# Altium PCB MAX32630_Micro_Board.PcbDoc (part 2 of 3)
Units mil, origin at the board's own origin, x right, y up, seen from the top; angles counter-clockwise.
Board outline 1192.91 x 1079.23 mil, 6 copper layers (Top Layer, Ground Plane +, Mid-Layer 2, Mid-Layer 3, Power Plane 1.8v, Bottom Layer), stack 51.6 mil thick; 105 components, 122 nets, 1109 pads, 512 vias.
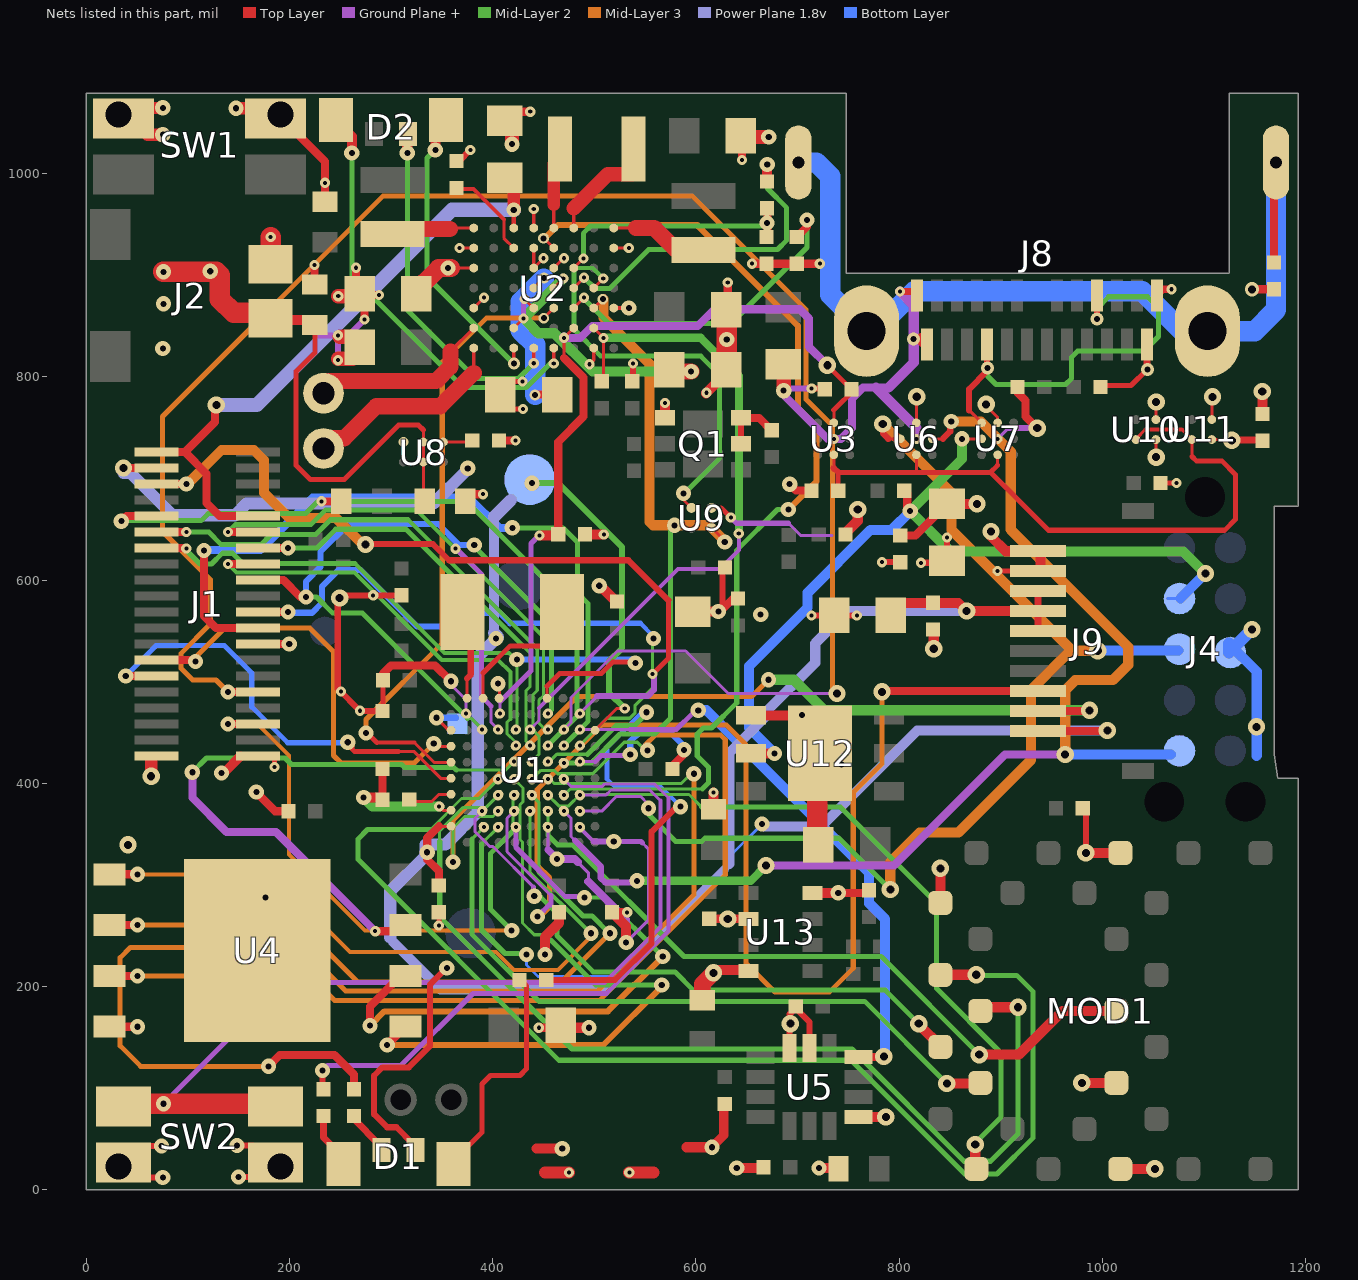
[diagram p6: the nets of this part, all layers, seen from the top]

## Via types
v1: diameter 15, hole 6, Top Layer to Bottom Layer, tented both sides, 180 vias
v2: diameter 10, hole 4, Top Layer to Ground Plane +, tented both sides, 134 vias
v3: diameter 17, hole 8, Top Layer to Bottom Layer, tented both sides, 82 vias
v4: diameter 10, hole 4, Ground Plane + to Mid-Layer 2, tented both sides, 57 vias
v5: diameter 12.8, hole 6, Top Layer to Bottom Layer, tented both sides, 20 vias
v6: diameter 10, hole 4, Top Layer to Ground Plane +, tented top, 16 vias
v7: diameter 10.63, hole 5.91, Top Layer to Bottom Layer, tented both sides, 13 vias
v8: diameter 10, hole 4, Ground Plane + to Mid-Layer 2, 5 vias
v9: diameter 11.81, hole 5.91, Top Layer to Bottom Layer, tented both sides, 3 vias
v10: diameter 14.17, hole 6, Top Layer to Bottom Layer, tented both sides, 1 vias
v11: diameter 14, hole 8, Top Layer to Bottom Layer, tented both sides, 1 vias

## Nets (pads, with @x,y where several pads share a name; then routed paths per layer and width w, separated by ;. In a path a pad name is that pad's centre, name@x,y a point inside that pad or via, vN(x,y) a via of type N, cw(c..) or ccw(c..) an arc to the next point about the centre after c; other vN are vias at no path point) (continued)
3V: C9.1 C12.2 C19.1 C37.1 D1.2 J1.4 J9.6 J9.7 J9.8 U1.A2 U2.A5 | length 2295.2
  Top Layer w3: 347.17,357.67 U1.A2@359.02,357.67 ; v1@358.74,907.13 U2.A5@381.39,907.13
  Top Layer w6: D1.2@321.33,45.39 305.33,61.39 296.18,61.39 283.39,74.18 283.39,112.39 291.39,120.39 317.38,120.39 338.5,141.51 338.5,202 353.92,217.42 354.86,216.48 v1(354.86,218.06)
  Top Layer w7: J9.6@936.69,549.84 J9.7@936.69,569.53 J9.8@936.69,589.21
  Top Layer w8: v3(36.64,710.25) J1.4@69,710.25 ; C19.1@347,299.5 347,313.78 335.55,325.23 335.55,346.05 347.17,357.67
  Top Layer w10: C37.1@790.5,568.52 799.48,577.5 858.5,577.5 v3(866.5,569.5) J9.7@928.5,569.5
  Top Layer w18: C9.1@321.33,881.39 347.07,907.13 v1@358.74,907.13
  Power Plane 1.8v w8: 513.4,201.18 633.02,320.8
  Power Plane 1.8v w10: 302.12,243.75 348.78,197.1 509.31,197.1 513.4,201.18 ; v1@401.39,547.78 401.39,662.03 ; 633.02,320.8 633.02,429.76 667.96,464.7 667.96,469.13 717.51,518.68 717.51,537.66 749.38,569.53 ; 749.4,569.5 v3(866.5,569.5)
  Power Plane 1.8v w12: v3@36.64,705.67 43.25,705.67 85.04,663.89 146.19,663.89 157.69,675.39 341.89,675.39 v1@375.5,709 ; 299.27,248.27 299.27,293.93 334.07,328.73 334.07,339.69 v1@335.23,338.53 ; v1@335.23,338.51 335.38,338.37 v1@335.68,338.07 ; v1@335.23,339.39 v1@335.23,338.53 ; v1@401.39,547.78 405.2,543.97 v1@403.62,542.39 ; 401.39,662.03 418.07,678.71 ; v1(403.39,542.39) v1@403.62,542.39 ; v1@335.23,338.53 v1@335.38,338.39 ; v1@335.23,338.53 v1@335.38,338.39 ; v1@335.38,338.39 336.68,339.69 353.69,339.69 385.39,371.39 385.39,524.16 v1@403.62,542.39
  other v1: 335.55,332.08 375.5,710 355.93,907.12
3V3_SFO: C10.2 C11.2 C17.1 C27.1 C47.1 R18.1 U1.D9 U2.F2 U3.C2 U6.C2 U7.C2 U10.B1 U11.B1 | length 1054.6
  Top Layer w3: C17.1@463.5,644 C17.1@464.5,645 ; 470.18,818.7 v6(470.18,838.44) U2.F2@479.81,848.07 ; v3@729.39,811.39 v3(729.39,811.48) ; U3.C2@735.75,754.75 735.75,767.36 ; C11.2@752.39,788.39 C11.2@756.78,788.39 ; U6.C2@817,754.75 v3@817,783 ; v3@877.5,675 v3@878,675.5 ; v3@886,771 897,760 U7.C2@897,754.75 ; v3@1053,724 U10.B1@1053,738.31 ; U11.B1@1108,738.31 1127.31,738.31 v3@1127.63,738
  Top Layer w5: v3@729.39,811.39 C11.2@752.39,788.39 ; 735.75,767.36 C11.2@756.78,788.39
  Top Layer w7: v3@1127.63,738 C10.2@1157.78,738
  Top Layer w8: C17.1@464.5,645 464.5,736 489.39,760.89 489.39,799.5 470.18,818.7 ; v1(692.31,694.39) 698.7,688 R18.1@715,688 ; C27.1@801.25,644 816.15,644 C47.1@847.15,675
  Top Layer w10: v2(446,644) C17.1@463.5,644 ; C47.1@847.15,675 v3(876.68,675) v3@877.5,675
  Ground Plane + w3: v8(407.16,468.79) 407.16,480.16
  Ground Plane + w5: 407.16,480.16 437.68,510.68 437.68,636.04 v2@446.64,645
  Ground Plane + w8: v6(470.18,838.44) 486.18,838.39 497.96,850.17 601.89,850.17 618.22,866.5 702.32,866.5 711.46,857.36 711.46,829.41 v3(729.39,811.48)
  Ground Plane + w10: v6(470.18,838.44) v6(470.18,838.44)
  other v3: 1053,721 1127.5,737.5 885.68,772.99 817.39,780.39
  other v6: 407.16,468.79
5V0_B: C38.1 J1.2 J1.9 U2.C7 | length 639.1
  Top Layer w3: C38.1@409.39,994.39 C38.1@420.76,983.02
  Top Layer w4: U2.C7@420.76,946.5 v10(420.76,964.39)
  Top Layer w8: J1.2@69,726 97,726 ; v3@126.61,773.61 126.61,755.61 97,726 ; J1.9@169,663.01 131.27,663.01 118.39,675.89 118.39,704.61 97,726
  Top Layer w12: v10(420.76,964.39) C38.1@420.76,994.39
  Power Plane 1.8v w14: v3(128,772.21) 167.88,772.21 360.06,964.39 v10(420.76,964.39)
32KIN: U1.B10 X1.2 | length 81.3
  Top Layer w3: U1.B10@374.76,483.65 374.76,503.24 ; X1.2@374.76,562 374.76,542.41 X1.2@378.39,538.79
  Top Layer w6: 374.76,503.24 378.39,506.87 X1.2@378.39,538.79
32KOUT: U1.C10 X1.1 | length 120
  Top Layer w3: U1.C10@390.51,483.65 390.51,508.51
  Top Layer w5: 390.51,508.51 390.58,508.51 417.34,535.28 X1.1@456.53,535.28
  Top Layer w7: X1.1@456.53,535.28 X1.1@469.25,548
AIN0: J1.30 U1.A5 | length 439.7
  Top Layer w3: 307.39,431.39 322.39,431.39 348.86,404.91 U1.A5@359.02,404.91
  Top Layer w5: v1@261.39,441.39 261.39,433.89 263.89,431.39 307.39,431.39
  Top Layer w8: v1(38.89,505.53) J1.30@69,505.53
  Bottom Layer w5: v1(38.89,505.53) 68.88,535.52 135.83,535.52 162.89,508.46 162.89,475.22 198.22,439.89 v1@259.89,439.89
  other v1: 257.39,440.39
AIN1: U1.A6 U2.E3 | length 625.7
  Top Layer w3: v1@274.39,449.39 v1(275.39,449.39) ; 322.98,440.02 342.34,420.66 U1.A6@359.02,420.66 ; v7@449.96,857.59 U2.E3@460.13,867.76
  Top Layer w4: 285.98,440.02 322.98,440.02
  Top Layer w5: v1@276,450 285.98,440.02
  Mid-Layer 3 w5: v1(275.39,449.39) 275.39,462.78 350.39,537.78 350.39,814.39 394.13,858.13 v7@450.5,858.13
  Bottom Layer w5: v1(275.39,449.39) v1@276,450
  other v7: 450.37,857.76
AIN2: J1.28 U1.A7 | length 432.9
  Top Layer w3: v1@340.5,441.5 345.59,436.41 U1.A7@359.02,436.41
  Top Layer w8: J1.28@67.11,521.28 v1@106.11,521.28
  Mid-Layer 3 w5: v1(107.5,519.89) 107.5,524 136.27,552.77 220.01,552.77 243.39,529.39 243.39,427.39 250.89,419.89 322.89,419.89 v1(342,439)
AIN3: pad.2 U1.A8 | length 39
  Top Layer w3: v1@344.5,464.5 356.84,452.16 U1.A8@359.02,452.16
  Bottom Layer w6: v1(344.63,464.5) pad.2@363.99,464.5
BAT: C3.1 C40.1 J2.2 U2.H3 U8.A2 U8.B2 | length 568.8
  Top Layer w3: 331.84,747.66 U8.B2@331.84,716.16 331.84,678.66 C40.1@333,677.5
  Top Layer w4: U2.H3@519.18,867.76 v1@531.76,867.76
  Top Layer w5: C3.1@225,851 225,823.5 206.5,805 206.5,713 220.5,699 253.89,699 307.39,752.5 327,752.5 331.84,747.66
  Top Layer w10: J2.2@176.76,863 183.76,856 220,856 C3.1@225,851
  Top Layer w20: v1(75.89,903.39) 128.11,903.39 131.5,900 131.5,876.43 144.93,863 J2.2@176.76,863
  other v1: 534,867.76 122,904
DEBUG_ENABLE: R18.2 U3.A2 U6.A2 U7.A2 U10.A1 U11.A1 | length 668.9
  Top Layer w3: 735.75,710.25 U3.A2@735.75,723.25 ; R18.2@740,689.39 R18.2@741.39,688 ; 817,706 U6.A2@817,723.25 ; 897,713 U7.A2@897,723.25 ; U10.A1@1033.31,738.31 1033.31,739.18 1042.53,748.39 ; 1078.24,748.39 1088.31,738.31 1088.31,721.69
  Top Layer w4: 1042.53,748.39 1078.24,748.39
  Top Layer w5: R18.2@740,689.39 740,706 817,706 890,706 ; 897,713 890,706 ; 1088.31,721.69 1092.99,717.01 1117.99,717.01 1131,704 1131,659.5 1120.5,649 947,649 890,706
  Top Layer w6: 735.75,710.25 740,706
GND: C1.2 C2.2 C3.2 C4.2 C5.2 C6.2 C7.1 C8.1 C9.2 C10.1 C11.1 C12.1 C13.2 C14.2 C15.2 C16.2 C17.2 C18.2 C19.2 C20.2 C21.2 C22.2 C23.2 C24.2 C25.2 C26.2 C27.2 C28.2 C29.2 C30.2 C31.2 C32.2 C33.2 C34.2 C35.2 C36.2 C37.2 C38.2 C39.1 C40.2 C41.2 C42.2 C43.2 C44.2 C45.2 C46.2 C47.2 C48.2 J1.25 J1.39 J1.40 J2.1 J4.3 J8.A1 J8.A12 J8.B1 J8.B12 J9.9 J9.10 MOD1.1 MOD1.12 MOD1.14 MOD1.20 Q1.1 R2.1 R7.1 R11.2 R13.2 R19.1 RT1.1 SW1.3 SW1.4 SW2.3 SW2.4 U1.A3 U1.B9 U1.D10 U1.G2 U1.J2 U1.J6 U2.A3 U2.A6 U2.C2 U2.D3 U2.D5 U2.D6 U2.D7 U2.E5 U2.G1 U2.H6 U3.B2 U4.4 U4.EP U5.1 U5.6 U5.7 U6.B2 U7.B2 U8.A1 U9.B1 U10.B2 U11.B2 U12.1 U12.EP U13.1 U13.5 U13.7 | length 4527.6
  Top Layer w3: J1.39@169,426.79 181.49,426.79 J1.39@185.39,422.89 ; v2(181.5,937.5) v2@183.5,939.5 ; SW1.3@186.19,1051.95 SW1.3@195.05,1051.95 ; v2@231,678 v2(231.5,677.5) ; 290.39,392.39 291.61,391.17 C15.2@291.61,386 ; C22.2@291.61,471 C22.2@292,471.39 ; C44.2@292,501.39 C44.2@292,508 ; v2(347.39,377) 350.97,373.42 U1.A3@359.02,373.42 ; C39.1@364.39,1012.39 C39.1@367,1012.39 ; v2(367.39,926.81) U2.A6@381.39,926.81 ; C40.2@373,677.5 C40.2@380,684.5 ; U2.A3@381.39,867.76 v2(391.55,877.93) ; U1.D10@406.52,483.91 406.52,498 v1@407.62,498 ; U2.C2@420.76,848.07 v2@430.93,858.24 ; v2(431.22,876.55) U2.D3@441.39,866.39 ; U2.D6@440.44,926.81 U2.D5@440.44,907.13 v2@450.61,917.3 ; U2.D7@440.44,946.5 v2(440.44,965.39) ; U2.E5@460.13,907.13 v2@470.3,917.3 ; v6(495.39,812.39) 499.5,816.5 U2.G1@499.5,828.39 ; U2.H6@519.18,926.81 v2(534,926.81) ; C24.2@576.89,414 C24.2@576.89,417.28 ; U9.B1@615.39,671.07 624.83,671.07 ; v1(615.94,41.78) v1@616.39,41.78 ; v1(622.14,569) v1@626.39,573.25 ; C42.2@626.39,608 C42.2@628.78,610.39 ; U13.7@651.07,266.61 U13.7@652.01,267.55 ; U12.EP@703.98,417.4 U12.EP@714,407.39 ; C45.2@719.39,340.39 C45.2@720.39,339.39 ; v2(735.75,739) U3.B2@736,739 ; C30.2@767.49,292.14 C30.2@768.74,293.4 ; J9.9@936.69,608.9 938.19,608.9 J9.9@939.19,607.9 ; C23.2@980.78,375.39 C23.2@983.87,372.3 ; v5@1044,807 v5(1044.39,807.39) ; U10.B2@1053,758 v3@1053,772.31 ; U11.B2@1108,758 v3@1108,780.31
  Top Layer w5: v2(185.39,415.89) J1.39@185.39,422.89 ; C22.2@292,471.39 C44.2@292,501.39 ; v2(347,260) C19.2@347,273.11 ; C36.2@414.5,795.39 v6(429.5,795.39) ; C36.2@415,768.5 v6(430,768.5) ; v1@624.39,571.25 v1@626.25,571.25 ; 624.83,671.07 v2(634.39,661.51) ; C43.2@636.78,581.78 C43.2@641.39,581.78 ; v2(897,608.9) J9.9@936.69,608.9 ; R11.2@998.39,790 999.77,791.39 1028.39,791.39 v5@1044,807 ; C4.2@1056.5,694.5 1057.39,695.39 v2(1073,695.39)
  Top Layer w6: SW2.3@59,43 v1(74,43) v1@74.61,43 ; SW2.3@60.39,12 v1(75.39,12) v1@76,12 ; v1(75.39,1038.39) v1@76,1038.39 ; v1(75.39,1064.78) v1@76,1064.78 ; v1@146.77,1064.39 v1(147.39,1064.39) ; v1@147.77,43.39 v1(148.39,43.39) SW2.4@163.39,43.39 ; v1@149.16,12.39 v1(149.78,12.39) SW2.4@164.78,12.39 ; C22.2@291.61,471 269.78,471 247.5,493.28 247.5,580.5 v3(249.39,582.39) 252,585 C16.2@310.39,585 ; C39.1@367,1012.39 v2(378,1023.39) ; R19.1@538,795.39 v2(538,813) ; v1@626.39,573.25 C42.2@626.39,608 ; U5.7@692.31,139.39 692.31,172.7 698.19,178.58 712,164.78 U5.6@712,139.39 ; v2(713.69,565) C37.2@731.68,565 ; v2(714,788.39) C11.1@730.39,788.39 ; C37.2@740.39,565 v2(758.39,565) ; v2(783.26,617.61) C27.2@801.26,617.61 ; v2(821.5,617) C47.2@839.5,617 ; C47.2@847.15,624 v2(847.15,642) ; v3(983.87,331.51) C23.2@983.87,372.3
  Top Layer w7: v2(801,884) J8.B1@817,884 ; v5@1044,807 J8.A1@1044,831.97 ; J8.B12@1053.84,880.21 1059.87,886.24 v2(1068,886.24)
  Top Layer w8: U4.4@22.72,160.39 v1(50.39,160.39) ; v3(41,339.4) v3@41,341 ; J1.39@151.79,426.79 J1.39@169,426.79 ; v1(167.39,391.39) 167.39,391 185.87,372.52 C46.2@199,372.52 ; J1.25@169,537.02 v1(199.76,537.02) ; SW1.3@195.05,1051.95 235,1012 C5.2@235,972.5 ; C3.2@224.5,895 v2(224.5,910) ; v2(231.5,677.5) C48.2@251,677.5 ; C9.2@265.33,892.39 v2(265.33,907.39) ; C9.2@271.61,880.39 271.72,880.5 v2(288,880.5) ; v6(274,856.61) C9.2@274,872.89 ; 291.61,391.17 C20.2@291.61,414 ; C44.2@292,508 300,516 343.4,516 v1(359.02,500.39) ; C40.2@380,684.5 v2(390.5,684.5) ; C41.2@406.27,737.5 v2(422.5,737.5) ; C38.2@422,1061 v2(437,1061) ; v2(445.39,159.39) C8.1@460.39,159.39 ; C34.2@517.39,273 v2(532.39,273) ; C24.2@576.89,417.28 v1@587.69,428.08 ; C35.2@613.26,266.61 U13.7@651.07,266.61 ; v3(617.39,213.39) v3@620.37,216.37 ; v1@626.25,571.25 C43.2@636.78,581.78 ; C2.2@631.39,877.93 v2(631.39,892.93) ; v2(645.39,1013.39) C7.1@645.39,1028.39 ; v2(655.39,911.39) R2.1@699.39,911.39 v2(722,911.39) ; v1(740.14,292.14) C30.2@767.49,292.14 ; R13.2@916.61,790 916.61,784.39 924.39,776.61 924.39,761.11 v3(936,749.5) ; v11@1149.15,886.24 R7.1@1169,886.24
  Top Layer w9: v1@136,411 J1.39@151.79,426.79 ; v1@615.96,42.21 627.39,53.64 C33.2@627.39,78.12
  Top Layer w10: U4.EP@151.39,287.39 v1(176.53,287.39) ; v1(273,386) C15.2@291.61,386 ; 443.39,40.39 v1(468.53,40.39) ; v1@451.39,232.39 451.39,248.75 465.39,262.75 C18.2@465.39,273 ; C8.1@469.63,159.39 v1(494.77,159.39) ; C17.2@491.89,645 v2(509.39,645) ; v1@504.39,595.39 505,595.39 521.61,578.78 C21.2@522.39,578.78 ; C34.2@517.39,273 531.39,259 v1(531.39,243.39) ; Q1.1@569.6,759.59 v2(569.6,774.39) ; 590.8,41.78 v1(615.94,41.78) ; C28.2@597,569 v1(622.14,569) ; v2@609.89,783.89 C1.2@624.39,798.39 ; C14.2@617.39,374.39 v2(617.39,391) ; v3@620.37,216.37 U13.5@652.01,216.37 ; v1(640.25,21.39) C32.2@665.39,21.39 ; U12.1@654.48,466.79 U12.EP@703.79,466.79 ; U13.1@715,292.14 v1(740.14,292.14) ; v1(721.25,21.39) C13.2@740.39,21.39 ; U12.EP@728.39,418.39 v1(743.39,418.39) ; C25.2@746.58,645.59 759.39,658.39 v3(759.39,669.39) ; U5.1@760.23,71.47 v3(787,71.47) ; v3@834.12,530.5 C12.1@834.12,549.61 ; MOD1.1@840.65,282.3 v3(840.65,316.25) ; v3(890.5,647.78) 890.5,642.89 905,628.39 J9.10@926,628.39 ; J9.9@939.19,607.9 J9.10@939.19,627.9 ; v3(979.93,105.13) MOD1.14@1013.88,105.13 ; v3(983.87,331.51) MOD1.20@1017.82,331.51 ; MOD1.12@1017.82,20.49 v3(1051.77,20.49) ; C10.1@1157.78,763.5 v3@1157.78,785.5
  Top Layer w12: SW1.4@60.39,1038.39 v1(75.39,1038.39) ; SW1.4@60.39,1064.78 v1(75.39,1064.78) ; v3(63.89,406.89) 63.89,424.39 J1.40@64.39,424.89 ; v1(147.39,1064.39) SW1.3@162.39,1064.39 ; 451.51,16.85 v6(475,16.85) ; v2(534.5,16.85) 558.39,16.85 ; J8.A12@822.04,837.39 J8.A12@827.46,831.97
  Top Layer w14: v6@248,817.89 C6.2@262,817.89 ; v2(248,879.39) 253.39,879.39 ; v2@249.5,839.39 C6.2@263.5,839.39 ; v1@419.13,1029.21 C38.2@419.13,1049.63 ; C7.1@651.14,1036.13 v1@671.57,1036.13 ; v1@686.39,786.58 C31.2@686.39,807
  Top Layer w16: C26.2@606.39,186.39 606.39,202.39 v3(617.39,213.39)
  Top Layer w20: J2.1@181.5,906 v2(181.5,937.5) ; C1.2@630.39,807.39 C2.2@630.39,866.39 ; C45.2@719.39,340.39 719.39,426.39 U12.EP@722.39,429.39
  Ground Plane + w3: 225.39,839.5 226.78,840.89 ; v1@357.25,498.62 373.88,481.99 v2(373.88,468.79) ; 454.4,334.6 v2(454.4,356.77) ; 483.79,322.39 494.12,312.06 494.12,303.37 ; v2@485.9,356.1 v2(485.9,356.77) ; v2(485.9,421.54) 500.93,421.54 ; v1(531.39,243.39) 553.18,265.18 553.18,335.45 547.42,341.22 ; v1(686.39,786.39) v1@688.39,788.39 ; 691.12,655.89 703.12,643.89 733.89,643.89 ; v2(897,739) 907.5,749.5
  Ground Plane + w4: v2@485.9,356.1 499.4,342.6
  Ground Plane + w5: v1@363,496.88 v1@363,498 ; v2(430.39,857.39) v2@430.39,875.72 ; 500.93,421.54 506.78,427.39 v1@532.39,427.39 ; v1(519.18,342.6) 546.03,342.6 547.42,341.22 ; v2(634.39,661.51) 640.01,655.89 691.12,655.89
  Ground Plane + w6: 226.78,840.89 v2(247.89,840.89) ; v6(247.89,816.39) v2(247.89,840.89) ; v6(274,856.61) 258.28,840.89 v2(247.89,840.89) ; 499.4,342.6 v1(519.18,342.6) ; v1@688.39,788.39 v2(714,788.39) ; 907.5,749.5 v3(936,749.5)
  Ground Plane + w7: 454.4,334.6 v1@463.61,325.39
  Ground Plane + w8: v1@463.61,325.39 480.79,325.39 483.79,322.39 ; 494.12,303.37 531.39,266.1 v1(531.39,243.39) ; v1(686.39,786.39) 686.39,782.39 729.78,739 v2(735.75,739) 743,739 753.53,749.53 753.53,778.53 764.39,789.39 789.62,789.39
  Ground Plane + w10: 777.39,789.39 817,749.78 v2(817,739) ; 789.62,789.39 814.39,814.15 v5(814.39,837.39) 814.39,870.61 v2(801,884)
  Mid-Layer 2 w10: v1@276.6,382.39 281.99,377 v2(347.39,377)
  Bottom Layer w3: v1@535.39,427.78 v1(535.39,428.39) ; v3@1147.02,551.02 v3(1147.39,551.39)
  Bottom Layer w6: v1(535.39,428.39) 535.39,441.2 545.08,450.89 574.08,450.89 587.39,437.58 v1@587.39,428.39
  Bottom Layer w10: J4.3@1124.61,537.36 1152,509.96 1152,427.22 1151.73,426.94
  Bottom Layer w12: J4.3@1124.61,537.36 1124.61,528.85 1147.02,551.26 v3@1147.02,551.02
  other v1: 451.39,231.39 463.39,325.39 133.05,410.02 588.39,432.89 704.39,467.39 405.2,498 663.78,566.02 504.91,594.39 75.39,827.91 630.39,836.89 75.89,871.89 419.13,1029.02 671.76,1036.13
  other v2: 269.27,471.39 250.61,490.39 282.39,585 312.16,735.84 610.39,784.39 450.07,916.76 470.15,916.76 235,991
  other v3: 693,163.39 631.39,266.39 1151.73,455.5 834.12,532.39 1053,775.31 1108.39,780.31 1157.5,785.5
  other v4: 347.39,377
  other v11: 1147.39,886.15
ID/R\S\T\: J8.A9 J8.B9 U7.C3 | length 432.9
  Top Layer w3: 869,767 U7.C3@881.25,754.75
  Top Layer w6: 869,767 869,788 886.52,805.52 J8.A9@886.52,831.97 ; v5(994.79,857) J8.B9@994.79,880.21
  Mid-Layer 2 w5: v5(887,808.76) 887,800.78 895.39,792.39 963.89,792.39 969.89,798.39 969.89,819.39 975.89,825.39 1041,825.39 1055.39,839.78 1055.39,867.89 1044.39,878.89 1006.39,878.89 994.79,867.29 v5(994.79,857)
IDRST: J4.9 R21.2 U7.B3 U12.2 | length 847.7
  Top Layer w3: v1(862,739) U7.B3@881.25,739
  Top Layer w8: R21.2@805.19,688 808,685.2 808,671.35 v1@811.39,667.96
  Top Layer w10: U12.2@654.48,429.39 v1(677.39,429.39)
  Mid-Layer 2 w10: v1(862,739) 862,719.09 v1(810.92,668) 850.92,628 1080,628 v3(1101.5,606.5)
  Bottom Layer w3: J4.9@1064,582 J4.9@1077,582
  Bottom Layer w10: v1(677.39,429.39) 652.39,454.39 652.39,515.39 652.45,515.39 710,572.93 710,587.5 771.9,649.4 792.83,649.4 v1@811.39,667.96 ; J4.9@1077,582 v3(1101.5,606.5)
NetC1_1: C1.1 U2.E4 | length 275.1
  Top Layer w3: U2.E4@460.13,887.44 v2@470.3,897.61 ; C1.1@568.26,806.39 C1.1@568.39,806.52
  Top Layer w16: C1.1@574.39,805.39 v1(595.39,805.39)
  Mid-Layer 2 w10: v2(469.47,896.78) 433.39,860.7 433.39,854.64 445.02,843 460.67,843 498.28,805.39 v1(595.39,805.39)
  other v4: 469.47,896.78
NetC15_1: C15.1 U1.A4 | length 46.9
  Top Layer w3: C15.1@318,389.17 325.05,382.11 340.11,382.11 347.17,389.17 U1.A4@359.02,389.17
NetC36_1: C36.1 U2.D4 | length 165.2
  Top Layer w3: U2.D4@440.44,887.44 v7@450.61,897.61
  Top Layer w8: v7@442,782.5 C36.1@463.5,782.5
  Bottom Layer w20: v7(441.78,782.28) 441.78,831.48 427.71,845.56 427.71,873.92 v7@450.22,896.44
  other v7: 450.39,897.39
NetC39_2: C39.2 U2.C6 | length 89.3
  Top Layer w3: 411,955.01 411,936.57 U2.C6@420.76,926.81
  Top Layer w4: C39.2@366.39,985 381.01,985 411,955.01
NetC41_1: C41.1 U8.A3 | length 29
  Top Layer w3: U8.A3@351.53,735.84 378.22,735.84 C41.1@379.88,737.5
NetD1_1: D1.1 R12.1 | length 235.5
  Top Layer w3: D1.1@354.39,25.39 D1.1@358.39,25.39
  Top Layer w5: D1.1@358.39,25.39 389.5,56.5 389.5,104 397.89,112.39 426.89,112.39 433.39,118.89 433.39,200.39 R12.1@427.39,206.39
NetD1_3: D1.3 R9.1 | length 43.8
  Top Layer w7: R9.1@261.89,70.89 290.18,42.6 D1.3@290.18,38.82
NetD1_4: D1.4 R10.1 | length 38.8
  Top Layer w7: R10.1@233.39,69 233.39,51.39 D1.4@248.39,36.39
NetD2_1: D2.1 U2.E1 | length 429.7
  Top Layer w3: D2.1@245.39,1052.39 D2.1@246,1053 ; v2(460.13,813) U2.E1@460.13,828.39
  Top Layer w10: D2.1@245.39,1052.39 261.39,1036.39 v1(261.39,1020.39)
  Mid-Layer 2 w5: v1(261.39,1020.39) 261.39,899.39 371.39,789.39 432.89,789.39 455.89,812.39 v4@460.13,812.39
  other v4: 460.13,813
NetD2_3: D2.3 U2.D1 | length 347.4
  Top Layer w3: v2(440.44,813.39) U2.D1@440.44,828.39
  Top Layer w10: v1(315.99,1020.39) 315.99,1038.21 D2.3@317,1039.22
  Mid-Layer 2 w5: v1(315.99,1020.39) 315.99,865.79 383.39,798.39 425.44,798.39 v2(440.44,813.39)
  other v4: 440.44,813.39
NetD2_4: D2.4 U2.C1 | length 281.6
  Top Layer w3: v9(420.76,813.39) U2.C1@420.76,828.39
  Top Layer w10: v1(343.6,1023.39) D2.4@343.6,1041.21
  Mid-Layer 2 w5: v1@343.39,1023.39 335.38,1015.38 335.38,898.4 v9@420.57,813.2
NetJ6_1: J6.1 U2.A2 | length 180.8
  Top Layer w3: 358.39,825.07 U2.A2@381.39,848.07
  Top Layer w16: J6.1@233.5,790 239.5,796 344.5,796 358.39,809.89 358.39,825.07
NetJ8_0: J8.0 R7.2 | length 892.7
  Top Layer w3: J8.0@1169,1008.97 J8.0@1171,1010.97
  Top Layer w8: R7.2@1169,912.63 J8.0@1169,1008.97
  Bottom Layer w3: J8.0@768.02,844.98 J8.0@775.66,844.98
  Bottom Layer w20: J8.0@700.93,1010.97 718.81,1010.97 732.39,997.39 732.39,880.6 J8.0@768.02,844.98 ; J8.0@775.66,844.98 815.08,884.39 1039.39,884.39 1078.81,844.97 J8.0@1103.45,844.97 1149.97,844.97 1171,866 J8.0@1171,1010.97
NetJ11_1: J11.1 U2.A1 | length 200.1
  Top Layer w3: 381.39,803.89 U2.A1@381.39,828.39
  Top Layer w16: J11.1@232.5,739.5 254,739.5 285.5,771 348.5,771 381.39,803.89
NetL1_1: L1.1 U2.H7 | length 97.2
  Top Layer w3: U2.H7@519.18,946.5 541.14,946.5
  Top Layer w16: 541.14,946.5 559.14,946.5 580.83,924.81 L1.1@607.39,924.81
NetL2_1: L2.1 U2.A7 | length 48.3
  Top Layer w3: 363.5,946.5 U2.A7@381.39,946.5
  Top Layer w16: L2.1@327.3,945.5 357.72,945.5
NetL3_1: L3.1 U2.F7 | length 91.9
  Top Layer w3: U2.F7@479.81,946.5 479.81,965.95
  Top Layer w14: 479.81,965.95 513.25,999.39 537,999.39 L3.1@538,1000.39
NetL3_2: L3.2 U2.E7 | length 80.5
  Top Layer w3: U2.E7@460.13,946.5 460.13,969.02
  Top Layer w12: 460.13,969.02 460.13,1009.74 466.39,1016 L3.2@466.39,1024.39
NetQ1_5: Q1.5 Q1.6 R20.1 | length 60.9
  Top Layer w6: Q1.5@644.4,734 Q1.6@644.4,759.59
  Top Layer w8: Q1.6@644.4,759.59 662.41,759.59 R20.1@674.61,747.39
NetR1_1: R1.1 U2.F4 | length 337.1
  Top Layer w3: U2.F4@479.81,887.44 v2(489.98,897.61) ; v1@670,1008.78 v1(670.22,1009)
  Top Layer w10: R1.1@670,992.39 v1@670,1008.78
  Mid-Layer 2 w5: v2(489.98,897.61) 500.7,886.89 515.11,886.89 553.61,925.39 680.39,925.39 689.39,934.39 689.39,966.39 670.39,985.39 v1@670.39,1009
  other v4: 489.98,897.61
NetR1_2: R1.2 RT1.2 U2.F5 | length 252
  Top Layer w3: U2.F5@479.81,907.13 v2@489.98,917.3 ; R1.2@670,966 R1.2@670.39,965.62
  Top Layer w8: RT1.2@670.39,937.78 R1.2@670.39,965.62
  Mid-Layer 2 w5: v4@489.28,916.93 489.28,941.28 496.39,948.39 667,948.39 v1(670,951.39)
  other v2: 489.39,916.39
  other v4: 489.39,916.39
NetR2_2: R2.2 U2.F3 | length 323.4
  Top Layer w3: U2.F3@479.81,867.76 v2(489.98,877.93)
  Top Layer w8: R2.2@699.39,937.78 709.39,947.78 v1(709.39,954.39)
  Mid-Layer 2 w5: v4@489.44,877.39 514.33,852.5 634.5,852.5 709.39,927.39 v1(709.39,954.39)
  other v4: 489.98,877.93
NetTP4_1: TP4.1 U1.K8 | length 323.5
  Top Layer w3: U1.K8@500.75,452.16 522.3,473.7 v2(530,473.7)
  Mid-Layer 2 w6: v1(438.65,695.39) 464.39,695.39 527.39,632.39 527.39,533.1 514.39,520.1 514.39,489.32 v2(530,473.7)
  other v4: 530,473.7
NetU2_G4: U2.G4 U9.B2 | length 417.3
  Top Layer w3: U2.G4@499.5,887.44 v2@509.67,897.61 ; v1(587.89,685.39) 587.89,678.89 U9.B2@595.7,671.07
  Mid-Layer 2 w4: 480,904 483.12,907.12 ; 483.12,906.99 498.5,906.99 ; 498.5,907.12 v2(508.84,896.78)
  Mid-Layer 2 w5: 480,904 480,846.78 506.39,820.39 604.89,820.39 623.39,801.89 623.39,720 588.78,685.39 v1(587.89,685.39)
  other v4: 508.84,896.78
P00_RX: MOD1.5 U1.C3 | length 589.2
  Top Layer w10: v3(819.39,163.39) 819.39,162.64 MOD1.5@841.95,140.08
  Ground Plane + w3: v2(389.63,372.52) 382.65,365.54 382.65,352.21 397.08,337.77 400.31,337.77 440.39,297.69
  Ground Plane + w5: v1@440.39,288.39 440.39,297.69
  Mid-Layer 2 w5: v1@440.39,288.39 446.89,288.39 463.19,272.08 463.19,250.08 498.89,214.39 579.39,214.39 597.39,196.39 786.39,196.39 v3(819.39,163.39)
  other v1: 440.89,288.89
P01_TX: MOD1.6 U1.C2 | length 672.5
  Top Layer w10: v3(847,104.51) MOD1.6@880.95,104.51
  Mid-Layer 2 w3: 379.5,344.87 v2(391.41,356.77)
  Mid-Layer 2 w5: 379.5,344.87 379.5,251.5 445.61,185.39 766.12,185.39 v3(847,104.51)
  other v4: 391.41,356.77
P02_CTS: MOD1.3 U1.D5 | length 1230.4
  Top Layer w10: MOD1.3@842.05,211.49 v3(876,211.49)
  Mid-Layer 2 w3: 338.78,354.39 369.39,385 386.35,385 v2(405.38,404.02)
  Mid-Layer 2 w5: 338.78,354.39 276.89,354.39 267.39,344.89 267.39,325.11 465.11,127.39 752.61,127.39 864.61,15.39 896.39,15.39 932,51 932,194.78 915.78,211 v3@876,211
  other v4: 405.38,404.02
P03_RTS: MOD1.4 U1.D4 | length 995
  Top Layer w10: MOD1.4@883.05,179.49 v3(917,179.49)
  Mid-Layer 2 w3: 347.89,342.89 347.89,353.22 370.67,376 393.1,376 v4(405.38,388.27)
  Mid-Layer 2 w5: 347.89,342.89 347.89,268.61 478.11,138.39 753.61,138.39 864,28 890,28 917,55 v3(917,179.49)
  other v2: 405.38,388.27
P04_SCK: J9.1 U1.D2 | length 927
  Top Layer w8: J9.1@936.69,451.42 v3@1005,451.42
  Mid-Layer 2 w3: 389,340.4 v2(405.38,356.77)
  Mid-Layer 2 w5: 389,340.4 389,255.5 412.11,232.39 v1@434.39,232.39
  Power Plane 1.8v w10: v1(665.1,359.8) 667.39,357.5 723.52,357.5 817.91,451.89 v3(1005,451.89)
  Bottom Layer w3: v1(433.39,231.39) 433.39,221.11 444.61,209.89 527.2,209.89 630.73,313.43 630.73,325.43 v1(665.1,359.8)
  other v4: 405.38,356.77
P05_MOSI: J9.2 U1.D3 | length 878.6
  Top Layer w8: J9.2@936.69,471.1 v3@987.5,471.1
  Mid-Layer 2 w3: v1@361,319 v1(361,322.39) 361,356.06 372.32,367.39 400.24,367.39 v4(405.38,372.52) v4@407.48,372.52
  Mid-Layer 2 w10: v1(671.39,501.89) 696.39,501.89 726.48,471.8 v3(987.5,471.8)
  Mid-Layer 3 w5: v1(361,322.39) 361,363.5 482.89,485.39 654.89,485.39 v1(671.39,501.89)
  other v2: 405.38,372.52
P06_MISO: J1.35 U1.E4 | length 601.3
  Top Layer w8: v1(139.54,458.28) J1.35@169,458.28
  Mid-Layer 2 w3: 420,353 420,387.15 v8@421.13,388.27
  Mid-Layer 2 w5: v1(418.69,255.08) 398,275.78 398,331 420,353
  Mid-Layer 3 w4: v1(139.54,458.28) 168.72,458.28 199.5,427.5 199.5,329.89 274.39,255 v1@418.69,255
  other v6: 421.03,388.27
  other v8: 421.03,388.27
P07_SSEL: J9.3 U1.E3 | length 1288.8
  Top Layer w8: v3@783.25,490.79 J9.3@936.69,490.79
  Ground Plane + w3: v2(421.13,372.52) 414.12,365.53 414.1,332.7 457.35,289.39
  Ground Plane + w5: v1(444.11,268.89) 457.24,282 457.24,280.51 457.34,280.4 457.35,289.39
  Mid-Layer 3 w3: v1(444.11,268.89) v1@446.89,268.89
  Mid-Layer 3 w5: v1@446.89,268.89 455.89,277.89 455.89,307.39 443.89,319.39 443.89,393.89 507.39,457.39 629.89,457.39 649.5,437.78 649.5,222.78 677.89,194.39 731.39,194.39 754.89,217.89 754.89,390.89 783.25,419.25 v3(783.25,490)
P10_SCLK: U1.E2 U4.6 | length 596.7
  Top Layer w3: U4.6@307.39,210.39 U4.6@314.06,210.39
  Top Layer w5: U4.6@307.39,210.39 U4.6@308.39,209.39
  Top Layer w8: v1(279.39,161.39) 279.39,180.39 U4.6@308.39,209.39
  Ground Plane + w5: v2(422.91,356.77) 422.91,336.87 471.39,288.39 v1@491,288.39
  Mid-Layer 2 w3: v1(567.39,229.39) v1@569,229.39
  Mid-Layer 2 w4: v1(490.39,287.39) 509.39,287.39
  Mid-Layer 2 w5: 509.39,287.39 v1(567.39,229.39)
  Mid-Layer 3 w4: v1(567.39,229.39) v1@569.07,229.39
  Mid-Layer 3 w6: v1(279.39,161.39) 293.39,175.39 513.39,175.39 v1(567.39,229.39)
P11_SDIO0: pad.1@421.13,404.02 U1.E5 U4.5 | length 636
  Top Layer w3: v1(296.18,142.39) v1@296.18,142.51 ; U4.5@308.39,160.39 U4.5@314.06,160.39
  Top Layer w8: v1@296.18,142.51 U4.5@314.06,160.39
  Mid-Layer 2 w3: v2(421.13,404.02) 429.89,395.25 429.89,381.78 426.89,378.79 426.89,344.61 429.39,342.11 429.39,262.39 440.89,250.89 451.89,250.89
  Mid-Layer 2 w5: 451.89,250.89 501.39,201.39 v1(566.39,201.39)
  Mid-Layer 3 w6: v1(296.18,142.39) 509,142.39 v1@567.19,200.58
  other v4: 421.13,404.02
P12_SDIO1: U1.F4 U4.2 | length 714.3
  Top Layer w3: U4.2@22.72,265.96 U4.2@24.15,267.39
  Top Layer w8: U4.2@22.72,260.39 v1(50.39,260.39)
  Mid-Layer 2 w3: v2(438.65,388.27) 445.5,381.42 445.5,312.78 ; v1@512.39,250 514.78,252.39 v1(515.39,252.39)
  Mid-Layer 2 w5: 445.5,312.78 489.01,269.26 497.9,269.26 v1@514.78,252.39
  Mid-Layer 3 w5: v1(50.39,260.39) 211.39,260.39 267.28,204.5 467.5,204.5 v1(515.39,252.39)
  other v4: 438.65,388.27
P13_SSEL: U1.F3 U4.1 | length 678.5
  Top Layer w8: U4.1@22.72,310.39 v1(50.39,310.39)
  Ground Plane + w4: v1@498,250 v1@498,255
  Mid-Layer 2 w3: 436.87,311.91 v2(436.87,372.52) ; v1@493.78,255 v1@498,255
  Mid-Layer 2 w4: 436.87,311.91 v1@493.78,255
  Mid-Layer 3 w4: v1(50.39,310.39) 183.39,310.39 259.78,234 403.39,234 421,216.39 464.39,216.39 v1@498,250
  other v1: 496.8,252.39
  other v4: 436.87,372.52
P14_SDIO2: U1.F5 U4.3 | length 1023
  Top Layer w8: U4.3@22.72,210.39 v1(50.39,210.39)
  Mid-Layer 2 w3: v2(438.65,404.02) 447.41,412.78 460.41,412.78 463.81,409.39 498.39,409.39 529.39,440.39 542.39,440.39 v1@550.39,432.39
  Mid-Layer 3 w5: v1(50.39,210.39) 220.39,210.39 244.39,186.39 505.39,186.39 628.89,309.89 628.89,442.89 624.39,447.39 559.96,447.39 550.39,437.82 v1@550.39,432.39
  other v1: 552.39,432.39
  other v4: 438.65,404.02
P15_SDIO3: pad.1@421.13,421.54 U1.E6 U4.7 | length 622.8
  Top Layer w3: U4.7@308.06,254.39 U4.7@314.06,260.39
  Top Layer w8: v2(284.39,254.39) U4.7@308.06,254.39
  Ground Plane + w8: v1(104.39,410.89) 104.39,385.72 138.11,352 186.78,352 v2(284.39,254.39)
  Mid-Layer 2 w3: 364.39,412.95 412.53,412.95 v2(421.13,421.54)
  Mid-Layer 2 w5: v1(104.39,410.89) 118.44,424.93 195.57,424.93 202,418.5 310.27,418.5 313.36,415.41 362,415.38 364.39,412.99
  other v4: 421.13,421.54
P16_BT_RST: MOD1.16 pad.1@454.4,372.52 U1.G3 | length 690.5
  Top Layer w10: v3(878.89,132.89) 917.89,132.89 961,176 MOD1.16@1013.88,176
  Mid-Layer 2 w3: 454.4,358.72 v4(454.4,372.52)
  Mid-Layer 2 w5: 454.4,358.72 454.4,348.75 463.76,339.39 478.39,339.39 588.39,229.39 782.39,229.39 v3(878.89,132.89)
  other v2: 454.4,372.52
P17_32KHZ: MOD1.8 U1.G4 | length 738.8
  Top Layer w3: MOD1.8@875,21.57 MOD1.8@876.09,20.49
  Top Layer w10: MOD1.8@875,21.57 v3(875,44.39)
  Mid-Layer 2 w3: v2(454.4,388.27) 464.9,377.77 474.86,377.77 485.98,388.89 593.33,388.89 605.72,376.5
  Mid-Layer 2 w5: 605.72,376.5 680.5,376.5 742.28,376.5 837.04,281.74 837.04,197.96 900.39,134.61 900.39,71.39 875,46 v3(875,44.39) v3@875,40
  other v4: 454.4,388.27
P20_RX: J4.8 U1.J3 U6.B3 | length 1149.5
  Top Layer w3: 789.39,739 U6.B3@801.25,739
  Top Layer w6: v3(784,753.69) 784,744.39 789.39,739
  Ground Plane + w3: v2(485.9,372.52) 507.41,372.52 521.77,386.89 545.67,386.89 v1@552.39,380.17
  Ground Plane + w5: v1@552.39,375.39 v1@552.39,380.17
  Mid-Layer 2 w3: v2(485.9,372.52) v4@486.15,372.52
  Mid-Layer 2 w5: v1@552.39,375.39 552.39,370.39 579.89,342.89 605.89,342.89 608.89,345.89 740.89,345.89 v3(791.39,295.39)
  Mid-Layer 3 w10: v3(784,753.69) 851.5,686.19 851.5,649.5 970.61,530.39 v3(995.5,530.39) 968.32,530.39 930,492.07 930,423 858.39,351.39 820.33,351.39 791.39,322.44 v3(791.39,295.39)
  Bottom Layer w10: v3(995.5,530.39) 995.94,530.83 J4.8@1075,530.83
  other v1: 553.39,375.39
  other v4: 485.9,372.52
P21_TX: J4.6 U1.H3 U6.B1 | length 1197.4
  Top Layer w3: U6.B1@832.75,739 843.14,739
  Top Layer w6: 843.14,739 850.39,746.25 v1@850.39,757.39
  Ground Plane + w3: v2(470.15,372.52) 477,365.67 477,347.58 481.07,343.51
  Ground Plane + w5: v1@540.39,302.39 v1(542,304)
  Ground Plane + w6: 481.07,343.51 506.39,318.19 506.39,306.7 510.7,302.39 v1@540.39,302.39
  Ground Plane + w8: v3(669,319) 795,319 904.39,428.39 v3(963.5,428.39)
  Mid-Layer 2 w3: v3(669,319) v3@673,323
  Mid-Layer 2 w8: v1(542,304) 654,304 v3(669,319)
  Mid-Layer 3 w10: v1(851.39,756) 880.5,756 910,726.5 910,649.61 1025.5,534.11 1025.5,516.55 1010.45,501.5 973.43,501.5 963.5,491.57 v3(963.5,428.39)
  Bottom Layer w10: v3(963.5,428.39) J4.6@1067.39,428.39
P22_ALRT: U1.H4 U2.E6 | length 979.2
  Top Layer w3: v7@449.96,936.98 U2.E6@460.13,926.81
  Mid-Layer 2 w3: v4(470.15,388.27) 476.26,394.39 606.39,394.39
  Mid-Layer 2 w5: 606.39,394.39 612.39,400.39 612.39,415.89 601.39,426.89 601.39,448.39 607.39,454.39 615.39,454.39 640.25,479.25 640.25,629.25 680.39,669.39 v1(691,669.39)
  Mid-Layer 3 w6: v7@451.04,936.26 464.17,949.39 601.39,949.39 700.39,850.39 700.39,768.89 718.89,750.39 718.89,697.28 v1(691,669.39)
  other v2: 470.15,388.27
  other v7: 449.96,936.39
P23_PUSHBTN1: SW2.1 SW2.2 U1.J4 | length 927.1
  Top Layer w20: SW2.1@36.2,84.56 SW2.2@192.39,84.56
  Ground Plane + w3: v2(485.9,388.27) 511.27,388.27 516.39,393.39 554.61,393.39 565,383
  Ground Plane + w4: 510.26,204 565,258.74 565,383
  Ground Plane + w5: v1(76,84.56) 195.44,204 510.26,204
P24_RED: pad.1@454.4,404.02 R9.2 U1.G5 | length 1249.2
  Top Layer w8: v1(179.39,121.39) 190.39,132.39 244.39,132.39 263.39,113.39 R9.2@263.39,98.78
  Mid-Layer 2 w3: v4@454.4,405.8 460.31,399.89 585.89,399.89 595.39,409.39 v1(598,409.39)
  Mid-Layer 3 w5: v1(179.39,121.39) 53.61,121.39 33.39,141.61 33.39,228.39 43.39,238.39 212.39,238.39 255.28,195.5 503.5,195.5 598,290 v1@598,411.39
  other v2: 454.4,404.02
  other v4: 454.4,404.02
P25_GRN: R10.2 U1.H5 | length 655.6
  Top Layer w6: R10.2@232.39,102.78 v1(232.39,117.39)
  Ground Plane + w3: v2(470.15,404.02) 477.17,397 508,397 510.39,399.39 559.15,399.39 573,385.54
  Ground Plane + w4: 511.81,193.19 573,254.39 573,385.54
  Ground Plane + w5: v1(232.39,117.39) 237.39,122.39 309.8,122.39 380.61,193.19 511.81,193.19
P26_BLU: pad.1@454.4,421.54 R12.2 U1.G6 | length 554.8
  Top Layer w6: R12.2@452.78,206.39 520.39,206.39 556.39,242.39 556.39,352.39 581,377 v1(585,377)
  Mid-Layer 2 w3: v8@454.4,419.76 463.19,428.56 493.3,428.56
  Mid-Layer 2 w5: 493.3,428.56 521.63,456.89 539.89,456.89 v1@552.39,469.39
  Bottom Layer w4: 512.39,404.24 519.24,397.39 564.61,397.39 v1(585,377)
  Bottom Layer w5: 512.39,404.24 512.39,435.03 546.75,469.39 v1@552.39,469.39
  other v1: 551.39,469.89
  other v6: 454.48,421.54
  other v8: 454.48,421.54
P27_MPC0: U1.H6 U2.G3 U9.A1 | length 669.1
  Top Layer w3: U2.G3@499.5,867.76 v7@509.67,877.93 ; U9.A1@615.39,651.39 628.39,638.39 v1(628.39,637.39)
  Mid-Layer 2 w5: v2(470.15,419.76) 496.76,419.76 525.39,448.39 559.39,448.39 575,464 575,650 v1(578.89,653.89)
  Mid-Layer 3 w10: v7@509.13,876.39 509.13,858.26 554.39,813 554.39,657.39 557.89,653.89 612.89,653.89 628.39,638.39 v1(628.39,637.39)
  other v4: 470.15,419.76
  other v7: 508.39,876.43
P30_RXD: J1.12 pad.1@438.65,421.54 U1.F6 | length 560.4
  Top Layer w8: J1.12@69,647.26 v4(98.46,647.26)
  Mid-Layer 2 w3: v2(438.65,421.54) 445.64,428.53 445.64,446.36 439.89,452.11 439.89,487.32 443.89,491.32 443.89,532.1
  Mid-Layer 2 w4: 316.6,659.39 443.89,532.1
  Mid-Layer 2 w5: v4(98.46,647.26) 120.52,647.26 132.89,634.89 171.89,634.89 181.89,644.89 225.89,644.89 240.39,659.39 316.6,659.39
  other v2: 98.46,647.26
  other v4: 438.65,421.54
P31_TXD: J1.15 U1.E7 | length 428.6
  Top Layer w8: v4(139.54,615.76) J1.15@169,615.76
  Mid-Layer 2 w3: 417.39,463.29 414,459.9 414,449 422.91,440.09 v2(422.91,437.29)
  Mid-Layer 2 w4: v4(139.54,615.76) 147.91,607.39 263.89,607.39 349.89,521.39 405.39,521.39 417.39,509.39 417.39,463.29
  other v2: 139.54,615.76
  other v4: 422.91,437.29
P32_CTS: J1.23 U1.H7 | length 744
  Top Layer w8: v1(115.89,629.08) 115.89,564.39 127.51,552.77 J1.23@169,552.77
  Mid-Layer 2 w5: v1(419.39,651.39) 469.26,651.39 483.39,637.26 483.39,587.33 494,576.72 494,461.15 v2(470.15,437.29)
  Bottom Layer w8: v1(115.89,629.08) 116.39,629.58 171.31,629.58 222.73,681 377,681 406.61,651.39 v1(419.39,651.39)
  other v4: 470.15,437.29
P33_RTS: J1.21 U1.J7 | length 603.1
  Top Layer w8: J1.21@169,568.52 v1(198.46,568.52)
  Mid-Layer 2 w3: v2(485.9,437.29) 512.6,464 535,464 539.89,468.89 539.89,476.39 557.39,493.89 v1@557.39,542
  Bottom Layer w4: 545.32,557.5 v1@557.39,545.43
  Bottom Layer w5: 417.13,557.5 545.32,557.5
  Bottom Layer w6: v1@199.12,567.87 222.37,567.87 231.95,577.45 231.95,593.45 248.47,609.97 269.81,609.97 325.61,554.16 349.15,554.16 362.38,567.39 407.24,567.39 417.13,557.5 ; v1@557.39,542 v1@557.39,545.43
  other v1: 558.39,542.39
  other v4: 485.9,437.29
P34_SDA: J1.10 U1.G7 | length 681.3
  Top Layer w8: v1(34.5,658) 39.51,663.01 J1.10@69,663.01
  Mid-Layer 2 w5: v1@34.5,658.5 113.11,658.5 120,665.39 215.89,665.39 228,677.5 374.28,677.5 483,568.78 483,465.9 v2(454.4,437.29)
  other v4: 454.4,437.29
P35_SCL: J1.13 U1.F7 | length 419.9
  Top Layer w8: J1.13@169,631.51 v1(198.46,631.51)
  Mid-Layer 2 w3: 430,534.78 436.89,527.89 436.89,495.15 433,491.26 433,441.16 v4(436.87,437.29)
  Mid-Layer 2 w5: v1(198.46,631.51) 227.01,631.51 245.5,650 314.78,650 430,534.78
  other v2: 436.87,437.29
P36_INT1: U1.J8 U5.4 | length 567.8
  Top Layer w3: v3@784.53,130.53 v3(785,131)
  Top Layer w8: U5.4@760.23,130.53 v3@784.53,130.53
  Ground Plane + w3: v2(485.9,453.04) 535.04,453.04
  Ground Plane + w5: 535.04,453.04 581.04,453.04 v1@597.89,469.89
  Bottom Layer w10: v1@602.09,473.09 603.39,471.8 610.41,471.8 770.51,311.7 770.51,281.89 786.29,266.11 786.29,134.29 v3@783,131
  other v1: 602.39,471.8
P37_INT: R4.1 U1.F8 U2.G2 | length 662.7
  Top Layer w3: U2.G2@499.5,848.07 509.25,838.32 509.25,795.39 R4.1@509.13,795.39
  Ground Plane + w3: v2(436.87,453.04) 445.6,461.77 445.61,473.95
  Ground Plane + w4: 445.61,473.95 582.43,610.78 623.58,610.78 642.39,629.59 v4@642.39,645.39
  Mid-Layer 2 w8: v2(509.13,838.39) 604.83,838.44 642.39,800.89 v4@642.39,645.39
  other v4: 642.2,645.76 509.13,838.39
P40_OWM: J1.6 U1.J9 | length 778.4
  Top Layer w5: v2(557.39,507.39) 572.89,522.89 572.89,580.11
  Top Layer w6: v3@271,632.39 274.11,635.5 341,635.5 357,619.5 533.5,619.5 572.89,580.11
  Top Layer w8: J1.6@69,694.5 v1(98.46,694.5)
  Ground Plane + w3: v2(485.9,468.79) 502.84,485.74
  Ground Plane + w6: 502.84,485.74 552.69,485.74 558.79,491.84 558.79,505.98 v2(557.39,507.39)
  Mid-Layer 3 w10: v1@98.46,693.39 133.04,727.96 165,727.96 175,717.96 175,686 200,661 246,661 v3@272,635
  other v3: 274.89,635
P41: J1.31 U1.H8 | length 1859.7
  Top Layer w8: v1(139.54,489.78) J1.31@169,489.78
  Ground Plane + w3: v2(470.15,453.04) 477,459.9 477,484.39 522.77,530.16 589.97,530.16 631.74,488.39 v3(738.89,488.39)
  Mid-Layer 3 w5: v1(139.54,489.78) 127.75,501.57 104.79,501.57 93.39,512.96 93.39,527.89 122.39,556.89 122.39,600.39 75,647.78 75,761 291.89,977.89 596.61,977.89 708.39,866.11 708.39,777.89 734.39,751.89 734.39,488.39 v3(738.89,488.39)
P50_SCLK: J1.11 U1.D8 U1.G8 | length 696.8
  Top Layer w8: v4(139.54,647.26) J1.11@169,647.26
  Ground Plane + w3: v4@361.43,631 364,631 v4@365,630 ; 398.56,475.83 398.56,459.86 v2(405.38,453.04) ; v2(454.4,453.04) v4@455.04,453.04
  Ground Plane + w5: v4@365,630 388.86,606.14 388.86,485.53 398.56,475.83
  Mid-Layer 2 w3: 449.96,543.81 449.96,486.08 445.5,481.62 445.5,459.4 451.9,453 v2(454.4,453.04) v2(454.4,453.04)
  Mid-Layer 2 w4: 324.94,668.83 449.96,543.81
  Mid-Layer 2 w5: v4(139.54,647.26) 147.16,654.89 221.39,654.89 235.33,668.83 324.94,668.83
  other v2: 139.54,647.26
  other v4: 454.4,453.04 363.39,630.89
P51_MOSI: J1.14 U1.E8 U1.G10 | length 705.8
  Top Layer w3: U1.G10@453.5,483.65 453.5,495.5
  Top Layer w5: 453.5,495.5 466,508 506.89,508 518.28,519.39 539.39,519.39 v1(540.39,518.39)
  Top Layer w8: J1.14@69,631.51 v2@98.46,631.51
  Mid-Layer 2 w3: v4(422.91,453.04) 423.15,453.04 424,453.9 v1@424,520.39
  Mid-Layer 2 w4: 264.39,616.39 352.39,528.39 416,528.39 v1@424,520.39
  Mid-Layer 2 w5: v4@97.62,630.16 112.01,615.76 123.26,615.76 133.89,626.39 143.89,626.39 153.89,616.39 264.39,616.39 ; v4(98.46,631) v4@99,631
  Bottom Layer w6: v1(423.79,521.89) 536.68,521.89 536.79,521.99 v1(540.39,518.39)
  other v2: 422.91,453.04 98.46,631
P52_MISO: J1.17 pad.1@454.4,468.79 U1.C8 U1.G9 | length 700.7
  Top Layer w8: J1.17@169,600.02 193.98,600.02 210.61,583.39 v1(216.39,583.39)
  Mid-Layer 2 w3: 375.39,463.89 378.78,463.89 v2(389.63,453.04)
  Mid-Layer 2 w5: v1(216.39,583.39) 226.61,583.39 242.61,567.39 271.89,567.39 375.39,463.89 ; v1@381.22,633.78 457.89,557.11 457.89,472.29 v2(454.4,468.79)
  Bottom Layer w6: v1(216.39,583.39) 216.39,598.75 230.55,612.91 230.55,627.8 258.13,655.38 346.18,655.38 367.16,634.39 379.61,634.39 v1@380.72,633.28
  other v1: 381.84,634.39
  other v4: 389.63,453.04 454.4,468.79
